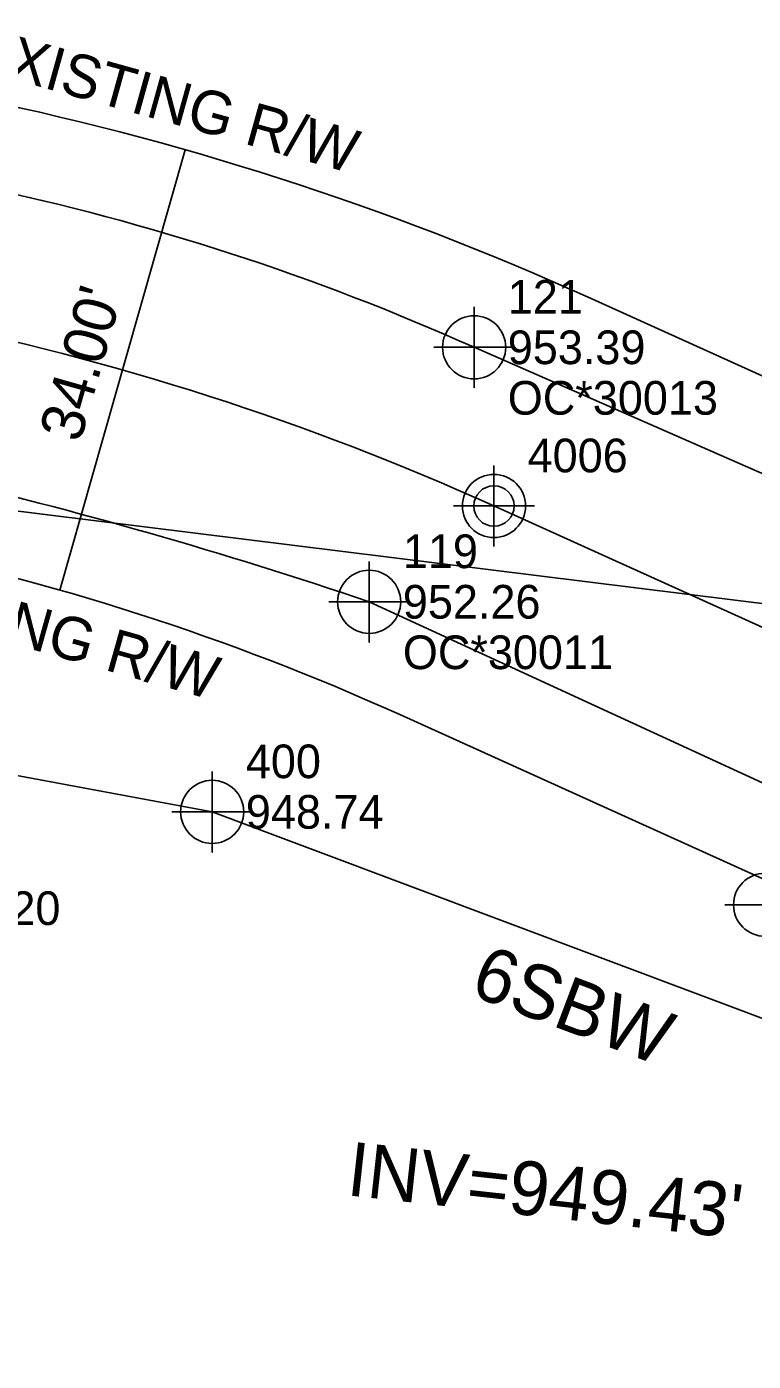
# Model space of a CAD drawing. Extents: x 1150279 to 1151282, y 655434 to 657999.
# Drawn here: x 1150841.1 to 1150895, y 657054.2 to 657153.3 of the extents above; entities that cross this region are included whole.
import ezdxf

# ---------------------------------------------------------------- set-up
doc = ezdxf.new("R2010")
doc.units = 0
for name, color, linetype in [('COGO Default Chain', 7, 'Continuous'), ('COGO Default Curve', 7, 'Continuous'), ('Cogo Default Point CELL', 7, 'Continuous'), ('COGO Default Point Number', 7, 'Continuous'), ('Exist Horizontal Alignment', 7, 'Continuous'), ('Exist Horizontal Alignment Station Label', 7, 'Continuous'), ('Exist Other Culture Fence Line', 7, 'Continuous'), ('Exist Other Culture Fence Line Cogo Comment', 7, 'Continuous'), ('Exist Other Culture Fence Line Cogo Elevation', 7, 'Continuous'), ('Exist Other Culture Fence Line Cogo Number', 7, 'Continuous'), ('Exist Other Culture Fence Line Cogo Point CELL', 7, 'Continuous'), ('Exist Other Culture Fence Line Text', 7, 'Continuous'), ('Exist Right of Way Line', 7, 'Continuous'), ('Exist Right of Way Line Text', 7, 'Continuous'), ('Exist Right of Way Width CELL', 7, 'Continuous'), ('Exist Roads EOP', 7, 'Continuous'), ('Exist Roads EOP Cogo Comment', 7, 'Continuous'), ('Exist Roads EOP Cogo Elevation', 7, 'Continuous'), ('Exist Roads EOP Cogo Number', 7, 'Continuous'), ('Exist Roads EOP Cogo Point CELL', 7, 'Continuous'), ('Exist Structure Minor Pipes CMP 15 Inch Text', 7, 'Continuous'), ('Exist Structure Minor Pipes CMP 18 Inch Cogo Point CELL', 7, 'Continuous')]:
    doc.layers.add(name, color=color, linetype=linetype)

msp = doc.modelspace()

# ---------------------------------------------------------------- linework, layer by layer
at = {"layer": 'COGO Default Chain'}
for p, q in [((1150614.756, 657145.261), (1150931.292, 657106.062)), ((1150875.785, 657117.706), (1150962.476, 657078.528))]:
    msp.add_line(p, q, dxfattribs=at)
msp.add_arc((1150793.42, 656935.454), 200, 65.68044, 91.66254, dxfattribs=at)
at = {"layer": 'COGO Default Curve'}
msp.add_arc((1150793.42, 656935.454), 200, 65.68044, 91.66254, dxfattribs=at)
at = {"layer": 'Cogo Default Point CELL'}
for points in [[(1150875.785, 657120.706), (1150875.785, 657117.706)], [(1150875.785, 657120.706), (1150875.785, 657117.706)], [(1150872.785, 657117.706), (1150875.785, 657117.706)], [(1150872.785, 657117.706), (1150875.785, 657117.706)], [(1150875.785, 657117.706), (1150878.785, 657117.706)], [(1150875.785, 657117.706), (1150875.785, 657114.706)], [(1150875.785, 657117.706), (1150878.785, 657117.706)], [(1150875.785, 657117.706), (1150875.785, 657114.706)]]:
    msp.add_lwpolyline(points, dxfattribs=at)
msp.add_circle((1150875.785, 657117.706), 2.344, dxfattribs=at)
msp.add_circle((1150875.785, 657117.706), 2.344, dxfattribs=at)
at = {"layer": 'Exist Horizontal Alignment'}
msp.add_line((1150875.785, 657117.706), (1150962.476, 657078.528), dxfattribs=at)
msp.add_arc((1150793.42, 656935.454), 200, 65.68044, 91.66254, dxfattribs=at)
at = {"layer": 'Exist Horizontal Alignment Station Label'}
msp.add_circle((1150875.785, 657117.706), 1.5, dxfattribs=at)
at = {"layer": 'Exist Other Culture Fence Line'}
msp.add_lwpolyline([(1151064.379, 657042.204), (1151035.792, 657039.664), (1150986.531, 657050.151), (1150941.416, 657063.204), (1150898.391, 657078.653), (1150854.858, 657094.994), (1150825.025, 657100.534), (1150812.457, 657091.594), (1150835.172, 657043.741), (1150852.719, 657007.431)], dxfattribs=at)
at = {"layer": 'Exist Other Culture Fence Line Cogo Point CELL'}
msp.add_lwpolyline([(1150854.858, 657097.994), (1150854.858, 657091.994), (1150854.858, 657094.994), (1150857.858, 657094.994), (1150851.858, 657094.994)], dxfattribs=at)
msp.add_circle((1150854.858, 657094.994), 2.344, dxfattribs=at)
at = {"layer": 'Exist Right of Way Line'}
for p, q in [((1150882.786, 657133.198), (1150944.003, 657105.532)), ((1150868.784, 657102.215), (1150930.001, 657074.549))]:
    msp.add_line(p, q, dxfattribs=at)
for radius in [217, 183]:
    msp.add_arc((1150793.42, 656935.454), radius, 65.68044, 91.66254, dxfattribs=at)
at = {"layer": 'Exist Right of Way Width CELL'}
for p in [(1150852.844, 657144.159), (1150843.533, 657111.459)]:
    msp.add_line(p, (1150848.434, 657128.672), dxfattribs=at)
at = {"layer": 'Exist Roads EOP'}
for p, q in [((1150919.164, 657109.821), (1150874.311, 657129.486)), ((1150910.091, 657090.545), (1150866.518, 657110.593))]:
    msp.add_line(p, q, dxfattribs=at)
for centre, major_axis, ratio, start_param, end_param in [((1150800.442, 656964.8), (-177.198, 34.758), 0.999524, 4.48455, 4.91412), ((1150752.571, 656773.823), (-278.809, 220.877), 0.99945, 5.05593, 5.247845)]:
    msp.add_ellipse(centre, major_axis=major_axis, ratio=ratio, start_param=start_param, end_param=end_param, dxfattribs=at)
at = {"layer": 'Exist Roads EOP Cogo Point CELL'}
for points in [[(1150874.311, 657132.486), (1150874.311, 657126.486), (1150874.311, 657129.486), (1150877.311, 657129.486), (1150871.311, 657129.486)], [(1150866.518, 657113.593), (1150866.518, 657107.593), (1150866.518, 657110.593), (1150869.518, 657110.593), (1150863.518, 657110.593)]]:
    msp.add_lwpolyline(points, dxfattribs=at)
for centre in [(1150874.311, 657129.486), (1150866.518, 657110.593)]:
    msp.add_circle(centre, 2.344, dxfattribs=at)
at = {"layer": 'Exist Structure Minor Pipes CMP 18 Inch Cogo Point CELL'}
msp.add_lwpolyline([(1150895.921, 657091.095), (1150895.921, 657085.095), (1150895.921, 657088.095), (1150898.921, 657088.095), (1150892.921, 657088.095)], dxfattribs=at)
msp.add_circle((1150895.921, 657088.095), 2.344, dxfattribs=at)

# ---------------------------------------------------------------- texts
at = {"layer": 'COGO Default Point Number'}
msp.add_text('4006', height=2.5, dxfattribs=at).set_placement((1150878.285, 657120.206))
at = {"layer": 'Exist Other Culture Fence Line Cogo Comment'}
msp.add_text('341028 EL*341020', height=2.5, dxfattribs=at).set_placement((1150814.957, 657086.594))
at = {"layer": 'Exist Other Culture Fence Line Cogo Elevation'}
msp.add_text('948.74', height=2.5, dxfattribs=at).set_placement((1150857.358, 657093.745))
at = {"layer": 'Exist Other Culture Fence Line Cogo Number'}
msp.add_text('400', height=2.5, dxfattribs=at).set_placement((1150857.358, 657097.495))
at = {"layer": 'Exist Other Culture Fence Line Text'}
msp.add_text('6SBW', height=4, rotation=339.42472, dxfattribs=at).set_placement((1150873.881, 657081.445))
at = {"layer": 'Exist Right of Way Line Text'}
for rotation, p in [(344.43549, (1150836.759, 657150.304)), (344.27394, (1150826.415, 657111.293))]:
    msp.add_text('EXISTING R/W', height=3.2, rotation=rotation, dxfattribs=at).set_placement(p)
at = {"layer": 'Exist Right of Way Width CELL'}
msp.add_text("34.00'", height=3.2, rotation=74.10706, dxfattribs=at).set_placement((1150845.042, 657122.328))
at = {"layer": 'Exist Roads EOP Cogo Comment'}
for s, p in [('OC*30013', (1150876.811, 657124.486)), ('OC*30011', (1150869.018, 657105.593))]:
    msp.add_text(s, height=2.5, dxfattribs=at).set_placement(p)
at = {"layer": 'Exist Roads EOP Cogo Elevation'}
for s, p in [('953.39', (1150876.811, 657128.236)), ('952.26', (1150869.018, 657109.343))]:
    msp.add_text(s, height=2.5, dxfattribs=at).set_placement(p)
at = {"layer": 'Exist Roads EOP Cogo Number'}
for s, p in [('121', (1150876.811, 657131.986)), ('119', (1150869.018, 657113.093))]:
    msp.add_text(s, height=2.5, dxfattribs=at).set_placement(p)
at = {"layer": 'Exist Structure Minor Pipes CMP 15 Inch Text'}
msp.add_text("INV=949.43'", height=4, rotation=353.6867, dxfattribs=at).set_placement((1150864.763, 657066.538))

doc.saveas('drawing.dxf')
